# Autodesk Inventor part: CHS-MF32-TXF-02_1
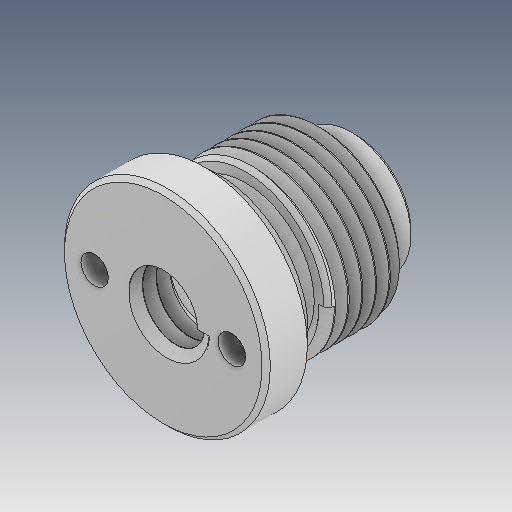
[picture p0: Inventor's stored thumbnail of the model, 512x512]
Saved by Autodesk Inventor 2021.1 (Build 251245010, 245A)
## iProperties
Created: 2021-05
Part Number: CHS-MF32-TXF-02_1
Material: Ogólny
Document SubType Name: Modeling
Designer: user
Density: 1 g/cm^3
Appearance: Domyślna
Author: user
Revision Number: ÈÎºÎ
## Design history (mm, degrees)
feature "ÊäÈë1"
node "Bryła1"
